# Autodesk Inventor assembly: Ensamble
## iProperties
Shininess: 64.0
Length Units: 11272
Angle Units: 11279
Time Units: 11290
Mass Units: 11286
Length Display Precision: 3
Angle Display Precision: 2
Compacted: True
Part Number: Ensamble
Document SubType Name: Assembly
Created: 2006-07
Designer: Gilberto Alvarez M
Manufacturer: Standard
Standards Organization: Custom
Density: 0.0
Volumn: 0.0
Area: 0.0
PropertySet Name: Model Information
Control State: 0
Master: False
Checked Out: False
Author: Gilberto Alvarez M
